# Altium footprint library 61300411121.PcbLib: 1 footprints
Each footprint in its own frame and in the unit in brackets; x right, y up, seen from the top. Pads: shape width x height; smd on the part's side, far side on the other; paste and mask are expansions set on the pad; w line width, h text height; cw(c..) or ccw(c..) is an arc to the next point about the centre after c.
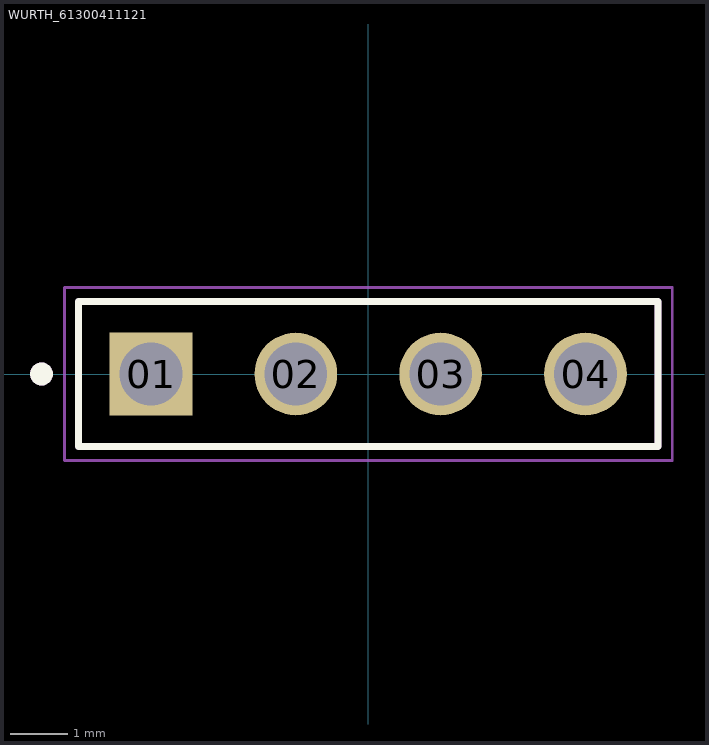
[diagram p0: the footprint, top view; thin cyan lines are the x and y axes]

## WURTH_61300411121 [mm]
pads (4):
  rect 1.45x1.45 hole 1.1: 01(-3.81,0)
  round 1.45 hole 1.1: 02(-1.27,0) 03(1.27,0) 04(3.81,0)
Top Overlay:
  circle w0.2: c-5.73,0 r0.1
  lines w0.127: -5.08,-1.27 5.08,-1.27 5.08,1.27 -5.08,1.27 -5.08,-1.27
Mechanical 13:
  circle w0.2: c-5.73,0 r0.1
  lines w0.127: -5.08,-1.27 5.08,-1.27 5.08,1.27 -5.08,1.27 -5.08,-1.27
Mechanical 15:
  lines w0.05: -5.33,-1.52 5.33,-1.52 5.33,1.52 -5.33,1.52 -5.33,-1.52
